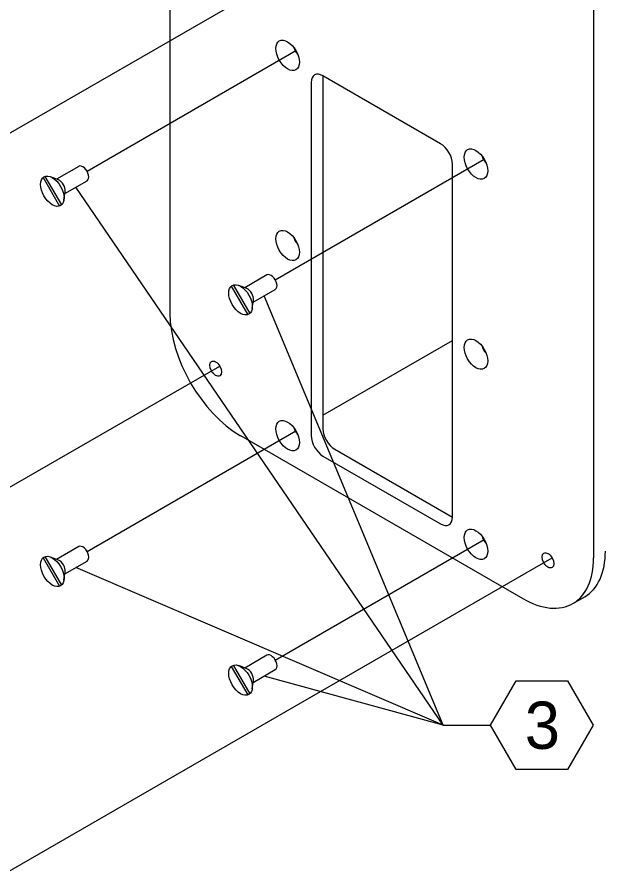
# Model space of a CAD drawing. Extents: x 99862 to 103151, y 100000 to 105076.
# Drawn here: x 102225 to 102423.3, y 104148.7 to 104438.5 of the extents above; entities that cross this region are included whole.
import ezdxf

# ---------------------------------------------------------------- set-up
doc = ezdxf.new("R2010")
doc.units = 0
for name, color, linetype in [('Level 15', 7, 'Continuous'), ('Level 16', 7, 'Continuous'), ('Level 20', 7, 'Continuous'), ('Level 41', 7, 'Continuous')]:
    doc.layers.add(name, color=color, linetype=linetype)

msp = doc.modelspace()

# ---------------------------------------------------------------- linework, layer by layer
at = {"layer": 'Level 15'}
for q in [(102244.83, 104380.98), (102308.47, 104344.24), (102244.83, 104252.38), (102308.47, 104215.64), (102385, 104199.01)]:
    msp.add_line((102369, 104199.01), q, dxfattribs=at)
at = {"layer": 'Level 16'}
for p, q in [((102213.93, 104394.31), (102405.77, 104505.07)), ((102248.58, 104386.39), (102319.19, 104427.16)), ((102312.22, 104349.65), (102382.83, 104390.42)), ((102328.31, 104303.83), (102372.06, 104329.09)), ((102220.72, 104278.45), (102293.44, 104320.44)), ((102248.58, 104257.79), (102319.19, 104298.56)), ((102312.22, 104221.05), (102382.83, 104261.82)), ((102220.72, 104148.74), (102405.77, 104255.58))]:
    msp.add_line(p, q, dxfattribs=at)
at = {"layer": 'Level 20'}
msp.add_lwpolyline([(102385, 104199.01), (102393.66, 104214), (102410.98, 104214), (102419.63, 104199.01), (102410.98, 104184.01), (102393.66, 104184.01), (102385, 104199.01)], dxfattribs=at)
at = {"layer": 'Level 41'}
for p, q in [((102276.6, 104568.28), (102276.6, 104338.27)), ((102419.79, 104485.61), (102419.79, 104255.6)), ((102324.33, 104416.35), (102324.33, 104296.94)), ((102328.31, 104418.65), (102328.31, 104299.23)), ((102368.09, 104395.68), (102328.31, 104418.65)), ((102245.76, 104388.01), (102238.27, 104383.69)), ((102372.06, 104269.38), (102372.06, 104388.79)), ((102233.71, 104384.26), (102239.3, 104374.58)), ((102234.36, 104384.63), (102239.95, 104374.96)), ((102238.91, 104383.43), (102236.21, 104384.5)), ((102241.08, 104378.81), (102248.58, 104383.14)), ((102240.76, 104376.63), (102241.18, 104379.5)), ((102309.4, 104351.27), (102301.91, 104346.94)), ((102297.35, 104347.52), (102302.94, 104337.84)), ((102298, 104347.89), (102303.59, 104338.21)), ((102302.55, 104346.69), (102299.85, 104347.76)), ((102304.72, 104342.07), (102312.22, 104346.4)), ((102304.4, 104339.89), (102304.82, 104342.75)), ((102300.47, 104296.94), (102395.93, 104241.82)), ((102332.29, 104292.35), (102372.06, 104269.38)), ((102328.31, 104290.05), (102368.09, 104267.08)), ((102245.76, 104259.42), (102238.27, 104255.09)), ((102233.71, 104255.66), (102239.3, 104245.98)), ((102234.36, 104256.04), (102239.95, 104246.36)), ((102238.91, 104254.83), (102236.21, 104255.9)), ((102241.08, 104250.22), (102248.58, 104254.54)), ((102240.76, 104248.03), (102241.18, 104250.9)), ((102412.8, 104240.15), (102416.78, 104242.45)), ((102309.4, 104222.67), (102301.91, 104218.35)), ((102297.35, 104218.92), (102302.94, 104209.24)), ((102298, 104219.29), (102303.59, 104209.62)), ((102302.55, 104218.09), (102299.85, 104219.16)), ((102304.72, 104213.47), (102312.22, 104217.8)), ((102304.4, 104211.29), (102304.82, 104214.16))]:
    msp.add_line(p, q, dxfattribs=at)
for centre, major_axis in [((102316.38, 104425.54), (-2.81, 4.87)), ((102380.02, 104388.79), (-2.81, 4.87)), ((102236.83, 104379.61), (-2.81, 4.87)), ((102316.38, 104361.24), (-2.81, 4.87)), ((102300.47, 104342.87), (-2.81, 4.87)), ((102380.02, 104324.49), (-2.81, 4.87)), ((102292.03, 104319.62), (-1.41, 2.44)), ((102316.38, 104296.94), (-2.81, 4.87)), ((102380.02, 104260.2), (-2.81, 4.87)), ((102236.83, 104251.01), (-2.81, 4.87)), ((102404.37, 104254.77), (-1.41, 2.44)), ((102300.47, 104214.27), (-2.81, 4.87))]:
    msp.add_ellipse(centre, major_axis=major_axis, ratio=0.57735, dxfattribs=at)
for centre, major_axis, start_param, end_param in [((102320.36, 104427.83), (-1.41, 2.44), 1.084101, 2.057491), ((102328.31, 104414.05), (-2.81, 4.87), 5.497787, 7.068583), ((102368.09, 104391.09), (-2.81, 4.87), 3.926991, 5.497787), ((102384, 104391.09), (-1.41, 2.44), 1.084101, 2.057491), ((102247.17, 104385.58), (1.41, -2.44), 6.28318, 9.424778), ((102247.17, 104385.58), (1.41, -2.44), 3.141593, 3.141605), ((102239.22, 104380.99), (1.41, -2.44), 0.630137, 2.511455), ((102320.36, 104363.53), (-1.41, 2.44), 1.084101, 2.057491), ((102310.81, 104348.84), (1.41, -2.44), 6.28318, 9.424778), ((102310.81, 104348.84), (1.41, -2.44), 3.141593, 3.141605), ((102302.86, 104344.24), (1.41, -2.44), 0.630137, 2.511453), ((102300.47, 104324.49), (16.88, -29.23), 3.926991, 5.497787), ((102384, 104326.79), (-1.41, 2.44), 1.084101, 2.057491), ((102320.36, 104299.23), (-1.41, 2.44), 1.084101, 2.057491), ((102332.29, 104296.94), (-2.81, 4.87), 0.785398, 2.356194), ((102328.31, 104294.64), (-2.81, 4.87), 0.785398, 2.356194), ((102368.09, 104271.68), (-2.81, 4.87), 2.356194, 3.926991), ((102384, 104262.49), (-1.41, 2.44), 1.084101, 2.057491), ((102247.17, 104256.98), (1.41, -2.44), 6.28318, 9.424778), ((102247.17, 104256.98), (1.41, -2.44), 3.141593, 3.141605), ((102399.91, 104271.68), (16.88, -29.23), 0, 0.785398), ((102239.22, 104252.39), (1.41, -2.44), 0.630137, 2.511455), ((102395.93, 104269.38), (16.88, -29.23), 6.283185, 7.068583), ((102395.93, 104269.38), (16.88, -29.23), 5.497787, 6.283185), ((102310.81, 104220.24), (1.41, -2.44), 6.28318, 9.424778), ((102310.81, 104220.24), (1.41, -2.44), 3.141593, 3.141605), ((102302.86, 104215.65), (1.41, -2.44), 0.630137, 2.511455)]:
    msp.add_ellipse(centre, major_axis=major_axis, ratio=0.57735, start_param=start_param, end_param=end_param, dxfattribs=at)

# ---------------------------------------------------------------- texts
at = {"layer": 'Level 20'}
msp.add_text('3', height=16, dxfattribs=at).set_placement((102396.54, 104191.01))

doc.saveas('drawing.dxf')
